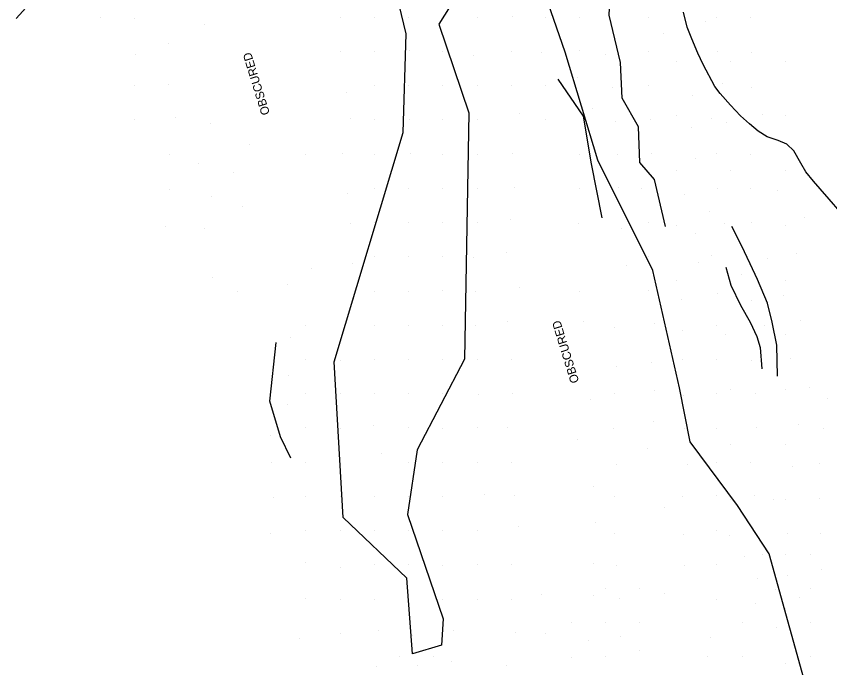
# Model space of a CAD drawing. Extents: x 524772 to 528246, y 273285 to 283088.
# Drawn here: x 527123.7 to 527268.6, y 274914.7 to 275030.7 of the extents above; entities that cross this region are included whole.
import ezdxf

# ---------------------------------------------------------------- set-up
doc = ezdxf.new("R2010")
doc.units = 0
for name, color, linetype in [('PH Exist DTM Breakline', 7, 'Continuous'), ('PH Exist DTM Obscure Area', 7, 'Continuous'), ('PH Exist DTM Obscure Area Text', 7, 'Continuous'), ('PH Exist DTM Point', 7, 'Continuous')]:
    doc.layers.add(name, color=color, linetype=linetype)

msp = doc.modelspace()

# ---------------------------------------------------------------- linework, layer by layer
at = {"layer": 'PH Exist DTM Breakline'}
for points in [[(527239.32, 274993.28), (527237.34, 275001.64), (527234.72, 275004.68), (527234.52, 275011.03), (527231.62, 275016.14), (527231.3, 275022.49), (527229.3, 275030.92), (527229.8, 275041.86), (527223.3, 275042.97), (527214.41, 275049.69), (527205.98, 275056.65), (527201.23, 275060.22), (527198.99, 275063.08), (527194.22, 275065.58)], [(527270.42, 274995.91), (527268.47, 274998.15), (527266.88, 274999.99), (527265.67, 275001.36), (527264.31, 275003.01), (527263.44, 275004.56), (527262.18, 275006.75), (527260.94, 275007.94), (527259.4, 275008.57), (527257.44, 275009.25), (527255.85, 275010.27), (527254.29, 275011.53), (527252.7, 275012.99), (527250.88, 275014.87), (527249.07, 275016.98), (527248.12, 275018.19), (527246.02, 275022.1), (527245.09, 275024.15), (527244.02, 275026.69), (527243.18, 275028.77), (527242.5, 275031.41)], [(527228.05, 274994.82), (527226.15, 275004.43), (527224.7, 275012.94), (527220.19, 275019.48)], [(527259.24, 274966.65), (527259.16, 274972.15), (527258.33, 274976.23), (527257.49, 274979.65), (527255.71, 274983.83), (527254.4, 274986.63), (527252.83, 274989.91), (527251.12, 274993.28)], [(527250.04, 274986.02), (527250.94, 274982.85), (527252.65, 274979.25), (527254.38, 274976.23), (527255.59, 274973.69), (527256.16, 274971.74), (527256.5, 274967.94)], [(527172.59, 274952.04), (527170.76, 274955.83), (527168.87, 274962.19), (527169.97, 274972.63)]]:
    msp.add_lwpolyline(points, dxfattribs=at)
at = {"layer": 'PH Exist DTM Obscure Area'}
for points in [[(527143.3, 275052), (527123.68, 275030.33)], [(527206.85, 275041.89), (527198.96, 275029.3), (527204.29, 275013.5), (527203.49, 274969.69), (527195.11, 274953.55), (527193.38, 274942), (527199.73, 274923.46), (527199.42, 274918.76), (527194.24, 274917.24), (527193.25, 274930.68), (527181.89, 274941.49), (527180.33, 274969.19), (527192.6, 275010.01), (527193.14, 275027.57), (527189.76, 275041.66)], [(527257.79, 274935.01), (527252.12, 274943.61), (527243.7, 274954.98), (527241.79, 274964.54), (527237.08, 274985.46), (527227.27, 275005.06), (527221.46, 275024.33), (527215.91, 275040.27)], [(527193.38, 274832.02), (527222.62, 274866.47), (527260.08, 274879.19), (527268.55, 274896.41), (527257.79, 274935.01)]]:
    msp.add_lwpolyline(points, dxfattribs=at)
at = {"layer": 'PH Exist DTM Point'}
for p, q in [((527212.13, 275030.65), (527212.13, 275030.65)), ((527138.69, 275030.56), (527138.69, 275030.56)), ((527144.79, 275030.22), (527144.79, 275030.22)), ((527157.29, 275029.27), (527157.29, 275029.27)), ((527181.36, 275030.56), (527181.36, 275030.56)), ((527187.46, 275030.56), (527187.46, 275030.56)), ((527193.55, 275030.56), (527193.55, 275030.56)), ((527199.66, 275030.55), (527199.66, 275030.55)), ((527205.75, 275030.56), (527205.75, 275030.56)), ((527217.98, 275030.42), (527217.98, 275030.42)), ((527224.03, 275030.56), (527224.03, 275030.56)), ((527236.23, 275030.56), (527236.23, 275030.56)), ((527246.41, 275029.75), (527246.41, 275029.75)), ((527248.42, 275030.56), (527248.42, 275030.56)), ((527254.53, 275030.5), (527254.53, 275030.5)), ((527238.89, 275027.57), (527238.89, 275027.57)), ((527150.82, 275025.77), (527150.82, 275025.77)), ((527144.91, 275023.91), (527144.91, 275023.91)), ((527181.37, 275024.44), (527181.37, 275024.44)), ((527187.46, 275024.47), (527187.46, 275024.47)), ((527193.79, 275024.54), (527193.79, 275024.54)), ((527199.65, 275024.47), (527199.65, 275024.47)), ((527205.2, 275023.76), (527205.2, 275023.76)), ((527211.85, 275024.47), (527211.85, 275024.47)), ((527217.28, 275024.27), (527217.28, 275024.27)), ((527223.98, 275024.64), (527223.98, 275024.64)), ((527228.67, 275023.98), (527228.67, 275023.98)), ((527236.23, 275024.47), (527236.23, 275024.47)), ((527248.59, 275024.52), (527248.59, 275024.52)), ((527254.56, 275024.33), (527254.56, 275024.33)), ((527241.22, 275022.72), (527241.22, 275022.72)), ((527250.97, 275022.74), (527250.97, 275022.74)), ((527260.72, 275022.74), (527260.72, 275022.74)), ((527223.65, 275019.84), (527223.65, 275019.84)), ((527144.79, 275018.37), (527144.79, 275018.37)), ((527150.84, 275018.5), (527150.84, 275018.5)), ((527187.46, 275018.35), (527187.46, 275018.35)), ((527193.56, 275018.35), (527193.56, 275018.35)), ((527199.65, 275018.36), (527199.65, 275018.36)), ((527205.75, 275018.34), (527205.75, 275018.34)), ((527211.83, 275018.42), (527211.83, 275018.42)), ((527217.94, 275018.32), (527217.94, 275018.32)), ((527229.86, 275018), (527229.86, 275018)), ((527236.26, 275018.38), (527236.26, 275018.38)), ((527249.55, 275018.71), (527249.55, 275018.71)), ((527254.63, 275017.98), (527254.63, 275017.98)), ((527182.58, 275017.22), (527182.58, 275017.22)), ((527244.15, 275016.55), (527244.15, 275016.55)), ((527213.37, 275013.45), (527213.37, 275013.45)), ((527226.24, 275014.22), (527226.24, 275014.22)), ((527144.79, 275012.27), (527144.79, 275012.27)), ((527152.08, 275012.64), (527152.08, 275012.64)), ((527183.28, 275012.51), (527183.28, 275012.51)), ((527187.46, 275012.27), (527187.46, 275012.27)), ((527193.78, 275012.27), (527193.78, 275012.27)), ((527199.65, 275012.27), (527199.65, 275012.27)), ((527205.75, 275012.25), (527205.75, 275012.25)), ((527217.94, 275012.27), (527217.94, 275012.27)), ((527230.43, 275012.06), (527230.43, 275012.06)), ((527236.62, 275012.4), (527236.62, 275012.4)), ((527241.22, 275012.99), (527241.22, 275012.99)), ((527247.44, 275012.49), (527247.44, 275012.49)), ((527250.22, 275011.77), (527250.22, 275011.77)), ((527256.61, 275013.14), (527256.61, 275013.14)), ((527260.72, 275012.99), (527260.72, 275012.99)), ((527158.2, 275011.65), (527158.2, 275011.65)), ((527243.87, 275010.96), (527243.87, 275010.96)), ((527165.28, 275007.95), (527165.28, 275007.95)), ((527150.92, 275006.06), (527150.92, 275006.06)), ((527175.27, 275006.16), (527175.27, 275006.16)), ((527181.76, 275006.23), (527181.76, 275006.23)), ((527187.46, 275006.18), (527187.46, 275006.18)), ((527193.81, 275006.24), (527193.81, 275006.24)), ((527199.65, 275006.18), (527199.65, 275006.18)), ((527205.75, 275006.18), (527205.75, 275006.18)), ((527212.13, 275006.35), (527212.13, 275006.35)), ((527224.03, 275006.18), (527224.03, 275006.18)), ((527230.73, 275006.05), (527230.73, 275006.05)), ((527236.8, 275006.35), (527236.8, 275006.35)), ((527248.39, 275006.26), (527248.39, 275006.26)), ((527254.51, 275006.18), (527254.51, 275006.18)), ((527244.69, 275005.42), (527244.69, 275005.42)), ((527156.14, 275004.49), (527156.14, 275004.49)), ((527241.22, 275003.24), (527241.22, 275003.24)), ((527250.94, 275003.25), (527250.94, 275003.25)), ((527260.71, 275003.21), (527260.71, 275003.21)), ((527162.45, 275002.83), (527162.45, 275002.83)), ((527212.38, 275000.24), (527212.38, 275000.24)), ((527230.88, 275000.19), (527230.88, 275000.19)), ((527150.94, 274999.88), (527150.94, 274999.88)), ((527182.7, 274999.16), (527182.7, 274999.16)), ((527187.47, 275000.09), (527187.47, 275000.09)), ((527193.61, 275000.09), (527193.61, 275000.09)), ((527199.65, 275000.08), (527199.65, 275000.08)), ((527205.75, 275000.07), (527205.75, 275000.07)), ((527224.04, 275000.03), (527224.04, 275000.03)), ((527235.1, 275000.1), (527235.1, 275000.1)), ((527242.72, 274999.06), (527242.72, 274999.06)), ((527248.49, 275000.12), (527248.49, 275000.12)), ((527254.52, 275000.06), (527254.52, 275000.06)), ((527259.22, 274999.61), (527259.22, 274999.61)), ((527158.5, 274998.54), (527158.5, 274998.54)), ((527163.94, 274996.85), (527163.94, 274996.85)), ((527247.1, 274995.99), (527247.1, 274995.99)), ((527211.69, 274994.58), (527211.69, 274994.58)), ((527264.14, 274994.81), (527264.14, 274994.81)), ((527150.27, 274993.29), (527150.27, 274993.29)), ((527157.27, 274992.97), (527157.27, 274992.97)), ((527183.24, 274993.73), (527183.24, 274993.73)), ((527187.46, 274993.99), (527187.46, 274993.99)), ((527193.56, 274993.95), (527193.56, 274993.95)), ((527199.65, 274994), (527199.65, 274994)), ((527205.75, 274993.99), (527205.75, 274993.99)), ((527223.76, 274993.9), (527223.76, 274993.9)), ((527236.2, 274994.07), (527236.2, 274994.07)), ((527241.22, 274993.48), (527241.22, 274993.48)), ((527249.83, 274993.82), (527249.83, 274993.82)), ((527254.61, 274994.01), (527254.61, 274994.01)), ((527260.72, 274993.48), (527260.72, 274993.48)), ((527231.54, 274992.92), (527231.54, 274992.92)), ((527244.71, 274992.1), (527244.71, 274992.1)), ((527211, 274988.68), (527211, 274988.68)), ((527187.46, 274987.89), (527187.46, 274987.89)), ((527193.55, 274987.89), (527193.55, 274987.89)), ((527199.66, 274987.87), (527199.66, 274987.87)), ((527205.16, 274987.71), (527205.16, 274987.71)), ((527236.34, 274987.92), (527236.34, 274987.92)), ((527247.5, 274988.19), (527247.5, 274988.19)), ((527257.43, 274987.52), (527257.43, 274987.52)), ((527262.61, 274988.49), (527262.61, 274988.49)), ((527176.2, 274985.87), (527176.2, 274985.87)), ((527183.62, 274986.73), (527183.62, 274986.73)), ((527232.31, 274986.36), (527232.31, 274986.36)), ((527245.25, 274986.86), (527245.25, 274986.86)), ((527158.62, 274984.26), (527158.62, 274984.26)), ((527252.88, 274984.69), (527252.88, 274984.69)), ((527171.92, 274983.02), (527171.92, 274983.02)), ((527241.22, 274983.73), (527241.22, 274983.73)), ((527260.72, 274983.73), (527260.72, 274983.73)), ((527163.07, 274981.79), (527163.07, 274981.79)), ((527187.46, 274981.79), (527187.46, 274981.79)), ((527193.55, 274981.79), (527193.55, 274981.79)), ((527199.65, 274981.81), (527199.65, 274981.81)), ((527205.47, 274981.69), (527205.47, 274981.69)), ((527213.31, 274982.47), (527213.31, 274982.47)), ((527224.03, 274981.79), (527224.03, 274981.79)), ((527236.21, 274981.87), (527236.21, 274981.87)), ((527248.56, 274981.34), (527248.56, 274981.34)), ((527183.8, 274980.45), (527183.8, 274980.45)), ((527242.13, 274980.2), (527242.13, 274980.2)), ((527254.71, 274980.09), (527254.71, 274980.09)), ((527260.29, 274980.96), (527260.29, 274980.96)), ((527175.28, 274975.7), (527175.28, 274975.7)), ((527187.45, 274975.71), (527187.45, 274975.71)), ((527193.57, 274975.66), (527193.57, 274975.66)), ((527199.65, 274975.7), (527199.65, 274975.7)), ((527205.49, 274975.62), (527205.49, 274975.62)), ((527211.12, 274976.31), (527211.12, 274976.31)), ((527224.73, 274976.32), (527224.73, 274976.32)), ((527237.37, 274976.04), (527237.37, 274976.04)), ((527248.35, 274975.72), (527248.35, 274975.72)), ((527256.87, 274975.57), (527256.87, 274975.57)), ((527263.36, 274976.5), (527263.36, 274976.5)), ((527181.89, 274974.27), (527181.89, 274974.27)), ((527230.17, 274975.37), (527230.17, 274975.37)), ((527242.31, 274974.76), (527242.31, 274974.76)), ((527172.44, 274973.55), (527172.44, 274973.55)), ((527250.05, 274974.01), (527250.05, 274974.01)), ((527260.72, 274973.98), (527260.72, 274973.98)), ((527261.6, 274969.81), (527261.6, 274969.81)), ((527175.27, 274969.6), (527175.27, 274969.6)), ((527181.42, 274969.4), (527181.42, 274969.4)), ((527187.46, 274969.6), (527187.46, 274969.6)), ((527193.56, 274969.6), (527193.56, 274969.6)), ((527199.65, 274969.62), (527199.65, 274969.62)), ((527205.76, 274969.55), (527205.76, 274969.55)), ((527211.84, 274969.6), (527211.84, 274969.6)), ((527230.58, 274968.35), (527230.58, 274968.35)), ((527236.79, 274969.12), (527236.79, 274969.12)), ((527242.33, 274969.54), (527242.33, 274969.54)), ((527248.43, 274969.57), (527248.43, 274969.57)), ((527254.69, 274969.45), (527254.69, 274969.45)), ((527172.15, 274966.69), (527172.15, 274966.69)), ((527237.41, 274964.01), (527237.41, 274964.01)), ((527250.97, 274964.22), (527250.97, 274964.22)), ((527260.72, 274964.22), (527260.72, 274964.22)), ((527265.01, 274964.66), (527265.01, 274964.66)), ((527175.28, 274963.51), (527175.28, 274963.51)), ((527181.36, 274963.51), (527181.36, 274963.51)), ((527187.46, 274963.49), (527187.46, 274963.49)), ((527193.6, 274963.5), (527193.6, 274963.5)), ((527199.66, 274963.51), (527199.66, 274963.51)), ((527206.01, 274963.29), (527206.01, 274963.29)), ((527212.07, 274963.62), (527212.07, 274963.62)), ((527230.16, 274963.51), (527230.16, 274963.51)), ((527242.49, 274963.12), (527242.49, 274963.12)), ((527248.42, 274963.51), (527248.42, 274963.51)), ((527255.32, 274963.64), (527255.32, 274963.64)), ((527268.2, 274962.66), (527268.2, 274962.66)), ((527172.05, 274961.52), (527172.05, 274961.52)), ((527226, 274962.45), (527226, 274962.45)), ((527237.22, 274958.54), (527237.22, 274958.54)), ((527175.26, 274957.42), (527175.26, 274957.42)), ((527181.36, 274957.41), (527181.36, 274957.41)), ((527187.35, 274957.93), (527187.35, 274957.93)), ((527193.55, 274957.42), (527193.55, 274957.42)), ((527199.65, 274957.41), (527199.65, 274957.41)), ((527205.85, 274957.42), (527205.85, 274957.42)), ((527211.2, 274957.57), (527211.2, 274957.57)), ((527230.14, 274957.4), (527230.14, 274957.4)), ((527242.73, 274957.33), (527242.73, 274957.33)), ((527248.42, 274957.41), (527248.42, 274957.41)), ((527255.59, 274957.43), (527255.59, 274957.43)), ((527262.92, 274957.98), (527262.92, 274957.98)), ((527267.44, 274957.25), (527267.44, 274957.25)), ((527169.03, 274956.01), (527169.03, 274956.01)), ((527223.61, 274955.42), (527223.61, 274955.42)), ((527250.98, 274954.45), (527250.98, 274954.45)), ((527260.72, 274954.47), (527260.72, 274954.47)), ((527188.82, 274952.88), (527188.82, 274952.88)), ((527236.19, 274953.71), (527236.19, 274953.71)), ((527169.17, 274951.31), (527169.17, 274951.31)), ((527175.27, 274951.31), (527175.27, 274951.31)), ((527181.36, 274951.31), (527181.36, 274951.31)), ((527193.55, 274951.31), (527193.55, 274951.31)), ((527199.65, 274951.31), (527199.65, 274951.31)), ((527205.75, 274951.31), (527205.75, 274951.31)), ((527211.91, 274951.31), (527211.91, 274951.31)), ((527243.31, 274950.98), (527243.31, 274950.98)), ((527248.42, 274951.31), (527248.42, 274951.31)), ((527254.52, 274951.29), (527254.52, 274951.29)), ((527266.67, 274951.03), (527266.67, 274951.03)), ((527230.54, 274950.87), (527230.54, 274950.87)), ((527261.89, 274950.58), (527261.89, 274950.58)), ((527226.41, 274946.99), (527226.41, 274946.99)), ((527175.27, 274945.22), (527175.27, 274945.22)), ((527181.36, 274945.22), (527181.36, 274945.22)), ((527187.46, 274945.22), (527187.46, 274945.22)), ((527193.55, 274945.22), (527193.55, 274945.22)), ((527199.66, 274945.19), (527199.66, 274945.19)), ((527207.08, 274945.59), (527207.08, 274945.59)), ((527212.43, 274945.39), (527212.43, 274945.39)), ((527230.15, 274945.15), (527230.15, 274945.15)), ((527242.34, 274945.15), (527242.34, 274945.15)), ((527248.35, 274945.45), (527248.35, 274945.45)), ((527255.1, 274945.39), (527255.1, 274945.39)), ((527169.53, 274944.98), (527169.53, 274944.98)), ((527250.96, 274944.73), (527250.96, 274944.73)), ((527258.47, 274944.74), (527258.47, 274944.74)), ((527260.72, 274944.71), (527260.72, 274944.71)), ((527266.81, 274944.88), (527266.81, 274944.88)), ((527239.08, 274943.21), (527239.08, 274943.21)), ((527213.12, 274939.82), (527213.12, 274939.82)), ((527226.77, 274940.65), (527226.77, 274940.65)), ((527169, 274938.6), (527169, 274938.6)), ((527175.26, 274939.22), (527175.26, 274939.22)), ((527181.36, 274939.12), (527181.36, 274939.12)), ((527187.53, 274939.14), (527187.53, 274939.14)), ((527193.55, 274939.12), (527193.55, 274939.12)), ((527199.66, 274939.09), (527199.66, 274939.09)), ((527205.75, 274939.12), (527205.75, 274939.12)), ((527230.28, 274938.65), (527230.28, 274938.65)), ((527242.51, 274938.45), (527242.51, 274938.45)), ((527248.42, 274939.12), (527248.42, 274939.12)), ((527250.67, 274938.27), (527250.67, 274938.27)), ((527255.05, 274939.26), (527255.05, 274939.26)), ((527261.01, 274938.64), (527261.01, 274938.64)), ((527266.86, 274938.63), (527266.86, 274938.63)), ((527256.58, 274934.98), (527256.58, 274934.98)), ((527253.3, 274934.5), (527253.3, 274934.5)), ((527260.72, 274934.96), (527260.72, 274934.96)), ((527265.19, 274934.96), (527265.19, 274934.96)), ((527175.17, 274933.45), (527175.17, 274933.45)), ((527181.5, 274932.56), (527181.5, 274932.56)), ((527187.46, 274933.03), (527187.46, 274933.03)), ((527193.55, 274933.04), (527193.55, 274933.04)), ((527199.58, 274933.01), (527199.58, 274933.01)), ((527205.75, 274933.03), (527205.75, 274933.03)), ((527211.84, 274933.03), (527211.84, 274933.03)), ((527226.56, 274933.25), (527226.56, 274933.25)), ((527230.56, 274932.91), (527230.56, 274932.91)), ((527242.7, 274932.96), (527242.7, 274932.96)), ((527248.42, 274933.03), (527248.42, 274933.03)), ((527267.08, 274932.31), (527267.08, 274932.31)), ((527255.74, 274930.7), (527255.74, 274930.7)), ((527261.11, 274931.16), (527261.11, 274931.16)), ((527228.6, 274928.84), (527228.6, 274928.84)), ((527234.68, 274928.91), (527234.68, 274928.91)), ((527239.22, 274927.89), (527239.22, 274927.89)), ((527258.92, 274928.72), (527258.92, 274928.72)), ((527265.16, 274928.85), (527265.16, 274928.85)), ((527175.23, 274927.05), (527175.23, 274927.05)), ((527181.36, 274926.93), (527181.36, 274926.93)), ((527187.45, 274926.94), (527187.45, 274926.94)), ((527193.55, 274926.94), (527193.55, 274926.94)), ((527199.65, 274926.93), (527199.65, 274926.93)), ((527205.75, 274926.93), (527205.75, 274926.93)), ((527211.87, 274926.94), (527211.87, 274926.94)), ((527217.22, 274927.69), (527217.22, 274927.69)), ((527226.44, 274927.61), (527226.44, 274927.61)), ((527231.17, 274927.04), (527231.17, 274927.04)), ((527248.42, 274926.93), (527248.42, 274926.93)), ((527263.16, 274927.28), (527263.16, 274927.28)), ((527255.32, 274926.12), (527255.32, 274926.12)), ((527260.72, 274925.21), (527260.72, 274925.21)), ((527222.5, 274922.76), (527222.5, 274922.76)), ((527228.6, 274922.76), (527228.6, 274922.76)), ((527234.69, 274922.76), (527234.69, 274922.76)), ((527252.98, 274922.76), (527252.98, 274922.76)), ((527265.16, 274922.76), (527265.16, 274922.76)), ((527181.36, 274920.83), (527181.36, 274920.83)), ((527188.13, 274921.29), (527188.13, 274921.29)), ((527201.61, 274921.43), (527201.61, 274921.43)), ((527212.6, 274921.03), (527212.6, 274921.03)), ((527217.94, 274920.83), (527217.94, 274920.83)), ((527259.12, 274921.91), (527259.12, 274921.91)), ((527174.08, 274920.03), (527174.08, 274920.03)), ((527194.34, 274920.45), (527194.34, 274920.45)), ((527225.58, 274919.55), (527225.58, 274919.55)), ((527231.38, 274920.31), (527231.38, 274920.31)), ((527247.4, 274920.11), (527247.4, 274920.11)), ((527234.7, 274917.87), (527234.7, 274917.87)), ((527192.01, 274916.68), (527192.01, 274916.68)), ((527198.08, 274916.68), (527198.08, 274916.68)), ((527222.52, 274916.59), (527222.52, 274916.59)), ((527228.6, 274916.67), (527228.6, 274916.67)), ((527246.88, 274916.67), (527246.88, 274916.67)), ((527252.98, 274916.67), (527252.98, 274916.67)), ((527265.19, 274916.67), (527265.19, 274916.67)), ((527187.89, 274914.98), (527187.89, 274914.98)), ((527195.12, 274915.13), (527195.12, 274915.13)), ((527201.12, 274915.93), (527201.12, 274915.93)), ((527210.92, 274915.09), (527210.92, 274915.09)), ((527260.72, 274915.45), (527260.72, 274915.45))]:
    msp.add_line(p, q, dxfattribs=at)

# ---------------------------------------------------------------- texts
at = {"layer": 'PH Exist DTM Obscure Area Text'}
for p in [(527168.87, 275013.38), (527223.95, 274965.66)]:
    msp.add_text('OBSCURED', height=1.524, rotation=107.1924, dxfattribs=at).set_placement(p)

doc.saveas('drawing.dxf')
